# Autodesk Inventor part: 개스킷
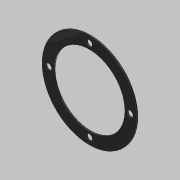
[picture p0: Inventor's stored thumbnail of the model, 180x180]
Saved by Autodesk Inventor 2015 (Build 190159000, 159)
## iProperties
Created: 2019-05
Part Number: 개스킷
Material: 고무
Document SubType Name: Modeling
Designer: mduedu
Density: 1 g/cm^3
Appearance: 고무 - 검은색 - 버전 1.1
Author: mduedu
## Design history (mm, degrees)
sketch "스케치1"
  geometry: C1 r 27 at (0, 0); C2 r 36 at (0, 0); 1 further point
  constraints: 2 centre point, 2 coincident
  dimensions: "d0" = 54 diameter of C1; "d1" = 72 diameter of C2
extrude "돌출1" new body sketch "스케치1" distance "d2" = 1; taper "d3" = 0 deg
sketch "스케치2" dims "d4" = 62
  geometry: C1 r 2.25 at (0, 31); 2 further points
  constraints: 2 vertical alignment, 1 centre point, 1 coincident, 2 other
  dimensions: "d5" = 4.5 diameter of C1
extrude "돌출2" cut sketch "스케치2" stored distance "d6" = 10; taper "d7" = 0 deg
node "솔리드1"
pattern_circular "원형 패턴1" dims angle "d9" = 360 deg
